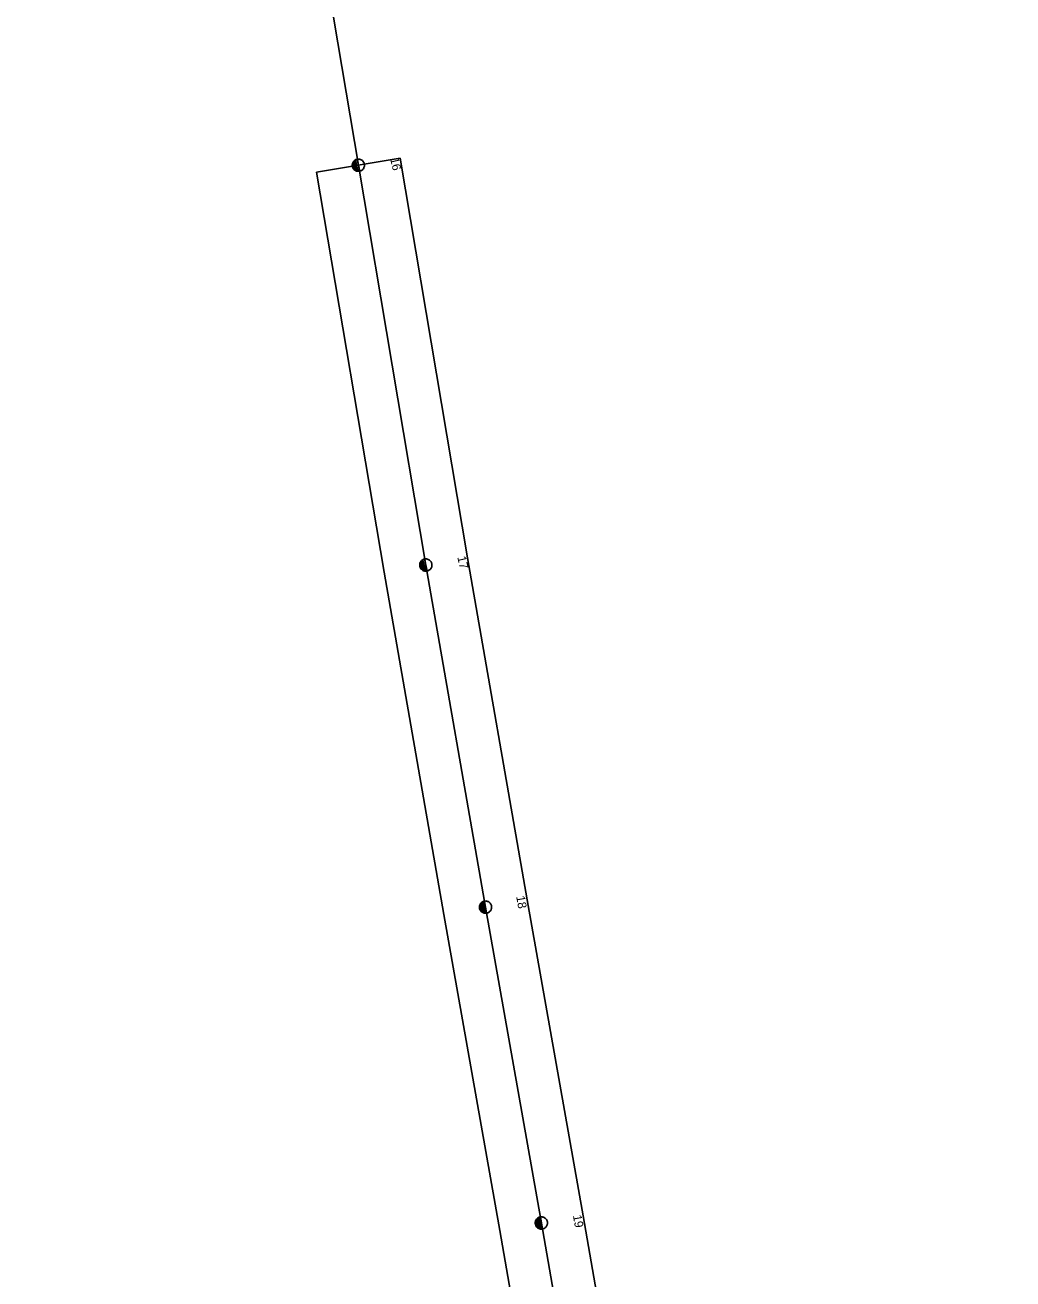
# Model space of a CAD drawing. Extents: x -762349 to -761250, y -1154000 to -1153000.
# Drawn here: x -761620.3 to -761422.1, y -1153503.2 to -1153251.6 of the extents above; entities that cross this region are included whole.
import ezdxf

# ---------------------------------------------------------------- set-up
doc = ezdxf.new("R2010")
doc.units = 0
for name, color, linetype in [('Vrstva 1', 7, 'Continuous'), ('Vrstva 13', 7, 'Continuous'), ('Vrstva 14', 7, 'Continuous'), ('Vrstva 35', 7, 'Continuous')]:
    doc.layers.add(name, color=color, linetype=linetype)

msp = doc.modelspace()

# ---------------------------------------------------------------- linework, layer by layer
at = {"layer": 'Vrstva 1'}
msp.add_lwpolyline([(-761620.31, -1153000), (-761604.55, -1153060.72), (-761583.29, -1153141.72), (-761565.07, -1153210.77), (-761553.44, -1153279.72), (-761539.9, -1153359.95), (-761527.93, -1153428.59), (-761516.72, -1153491.97), (-761505.02, -1153559.26), (-761494.37, -1153619.64), (-761482.3, -1153689.6)], dxfattribs=at)
at = {"layer": 'Vrstva 13'}
for points in [[(-761553.169, -1153280.908), (-761553.045, -1153280.873), (-761552.926, -1153280.825), (-761552.812, -1153280.764), (-761552.705, -1153280.693), (-761552.607, -1153280.61), (-761552.518, -1153280.518), (-761552.439, -1153280.416), (-761552.37, -1153280.308), (-761552.314, -1153280.192), (-761552.27, -1153280.071), (-761552.239, -1153279.946), (-761552.221, -1153279.819), (-761552.217, -1153279.69), (-761552.226, -1153279.562), (-761552.248, -1153279.435), (-761552.283, -1153279.312), (-761552.332, -1153279.193), (-761552.392, -1153279.079), (-761552.464, -1153278.973), (-761552.546, -1153278.874), (-761552.639, -1153278.785), (-761552.74, -1153278.705), (-761552.849, -1153278.637), (-761552.965, -1153278.581), (-761553.086, -1153278.537), (-761553.21, -1153278.506), (-761553.338, -1153278.488), (-761553.466, -1153278.483), (-761553.594, -1153278.492), (-761553.721, -1153278.515), (-761553.845, -1153278.55), (-761553.964, -1153278.598), (-761554.078, -1153278.659), (-761554.184, -1153278.731), (-761554.283, -1153278.814), (-761554.372, -1153278.906), (-761554.451, -1153279.007), (-761554.519, -1153279.116), (-761554.576, -1153279.232), (-761554.62, -1153279.353), (-761554.651, -1153279.478), (-761554.669, -1153279.604), (-761554.673, -1153279.733), (-761554.664, -1153279.862), (-761554.642, -1153279.988), (-761554.606, -1153280.112), (-761554.558, -1153280.231), (-761554.498, -1153280.344), (-761554.426, -1153280.451), (-761554.343, -1153280.549), (-761554.251, -1153280.639), (-761554.149, -1153280.718), (-761554.04, -1153280.786), (-761553.925, -1153280.842), (-761553.804, -1153280.886), (-761553.679, -1153280.918), (-761553.552, -1153280.935), (-761553.423, -1153280.94), (-761553.295, -1153280.931), (-761553.169, -1153280.908)], [(-761554.28, -1153278.876), (-761553.835, -1153280.803)], [(-761554.038, -1153278.643), (-761553.524, -1153280.869)], [(-761553.714, -1153278.51), (-761553.162, -1153280.903)], [(-761554.5, -1153279.203), (-761554.18, -1153280.587)], [(-761539.629, -1153361.138), (-761539.505, -1153361.103), (-761539.386, -1153361.055), (-761539.272, -1153360.994), (-761539.165, -1153360.923), (-761539.067, -1153360.84), (-761538.978, -1153360.747), (-761538.899, -1153360.646), (-761538.83, -1153360.537), (-761538.774, -1153360.422), (-761538.73, -1153360.301), (-761538.699, -1153360.176), (-761538.681, -1153360.049), (-761538.677, -1153359.92), (-761538.686, -1153359.792), (-761538.708, -1153359.665), (-761538.743, -1153359.542), (-761538.792, -1153359.422), (-761538.852, -1153359.309), (-761538.924, -1153359.203), (-761539.006, -1153359.104), (-761539.099, -1153359.015), (-761539.2, -1153358.935), (-761539.309, -1153358.867), (-761539.425, -1153358.811), (-761539.546, -1153358.767), (-761539.67, -1153358.736), (-761539.798, -1153358.718), (-761539.926, -1153358.713), (-761540.054, -1153358.722), (-761540.181, -1153358.745), (-761540.305, -1153358.78), (-761540.424, -1153358.828), (-761540.538, -1153358.889), (-761540.644, -1153358.961), (-761540.743, -1153359.043), (-761540.832, -1153359.136), (-761540.911, -1153359.237), (-761540.979, -1153359.346), (-761541.036, -1153359.462), (-761541.08, -1153359.582), (-761541.111, -1153359.707), (-761541.129, -1153359.834), (-761541.133, -1153359.963), (-761541.124, -1153360.092), (-761541.102, -1153360.218), (-761541.066, -1153360.342), (-761541.018, -1153360.461), (-761540.958, -1153360.574), (-761540.886, -1153360.681), (-761540.803, -1153360.779), (-761540.711, -1153360.869), (-761540.609, -1153360.948), (-761540.5, -1153361.016), (-761540.385, -1153361.072), (-761540.264, -1153361.116), (-761540.139, -1153361.148), (-761540.012, -1153361.165), (-761539.883, -1153361.17), (-761539.755, -1153361.161), (-761539.629, -1153361.138)], [(-761540.96, -1153359.433), (-761540.64, -1153360.817)], [(-761540.74, -1153359.106), (-761540.295, -1153361.033)], [(-761540.498, -1153358.873), (-761539.984, -1153361.099)], [(-761540.174, -1153358.739), (-761539.622, -1153361.133)], [(-761527.722, -1153429.791), (-761527.596, -1153429.763), (-761527.475, -1153429.721), (-761527.358, -1153429.666), (-761527.248, -1153429.6), (-761527.146, -1153429.523), (-761527.052, -1153429.435), (-761526.967, -1153429.338), (-761526.893, -1153429.233), (-761526.831, -1153429.121), (-761526.781, -1153429.002), (-761526.743, -1153428.879), (-761526.719, -1153428.753), (-761526.708, -1153428.625), (-761526.71, -1153428.496), (-761526.726, -1153428.368), (-761526.754, -1153428.244), (-761526.796, -1153428.122), (-761526.851, -1153428.005), (-761526.917, -1153427.895), (-761526.994, -1153427.792), (-761527.082, -1153427.698), (-761527.179, -1153427.614), (-761527.284, -1153427.54), (-761527.397, -1153427.478), (-761527.515, -1153427.428), (-761527.638, -1153427.39), (-761527.764, -1153427.365), (-761527.892, -1153427.354), (-761528.021, -1153427.356), (-761528.148, -1153427.372), (-761528.274, -1153427.401), (-761528.395, -1153427.443), (-761528.512, -1153427.497), (-761528.622, -1153427.564), (-761528.725, -1153427.641), (-761528.819, -1153427.728), (-761528.903, -1153427.825), (-761528.977, -1153427.931), (-761529.039, -1153428.043), (-761529.09, -1153428.162), (-761529.127, -1153428.285), (-761529.151, -1153428.411), (-761529.163, -1153428.539), (-761529.161, -1153428.668), (-761529.145, -1153428.795), (-761529.116, -1153428.921), (-761529.074, -1153429.042), (-761529.02, -1153429.159), (-761528.954, -1153429.269), (-761528.876, -1153429.371), (-761528.788, -1153429.466), (-761528.691, -1153429.55), (-761528.586, -1153429.623), (-761528.473, -1153429.686), (-761528.355, -1153429.736), (-761528.233, -1153429.774), (-761528.106, -1153429.798), (-761527.978, -1153429.809), (-761527.85, -1153429.807), (-761527.722, -1153429.791)], [(-761528.141, -1153427.367), (-761527.715, -1153429.787)], [(-761528.962, -1153428.019), (-761528.715, -1153429.417)], [(-761528.725, -1153427.704), (-761528.382, -1153429.651)], [(-761528.471, -1153427.484), (-761528.075, -1153429.733)], [(-761516.512, -1153493.171), (-761516.386, -1153493.143), (-761516.265, -1153493.101), (-761516.148, -1153493.046), (-761516.038, -1153492.98), (-761515.936, -1153492.903), (-761515.842, -1153492.815), (-761515.757, -1153492.718), (-761515.683, -1153492.613), (-761515.621, -1153492.501), (-761515.571, -1153492.382), (-761515.533, -1153492.259), (-761515.509, -1153492.133), (-761515.498, -1153492.005), (-761515.5, -1153491.876), (-761515.516, -1153491.748), (-761515.544, -1153491.624), (-761515.586, -1153491.502), (-761515.641, -1153491.385), (-761515.707, -1153491.275), (-761515.784, -1153491.172), (-761515.872, -1153491.078), (-761515.969, -1153490.994), (-761516.074, -1153490.92), (-761516.187, -1153490.858), (-761516.305, -1153490.808), (-761516.428, -1153490.77), (-761516.554, -1153490.745), (-761516.682, -1153490.734), (-761516.811, -1153490.736), (-761516.938, -1153490.752), (-761517.064, -1153490.781), (-761517.185, -1153490.823), (-761517.302, -1153490.877), (-761517.412, -1153490.944), (-761517.515, -1153491.021), (-761517.609, -1153491.108), (-761517.693, -1153491.205), (-761517.767, -1153491.311), (-761517.829, -1153491.423), (-761517.88, -1153491.542), (-761517.917, -1153491.665), (-761517.941, -1153491.791), (-761517.953, -1153491.919), (-761517.951, -1153492.048), (-761517.935, -1153492.175), (-761517.906, -1153492.3), (-761517.864, -1153492.422), (-761517.81, -1153492.539), (-761517.744, -1153492.649), (-761517.666, -1153492.751), (-761517.578, -1153492.846), (-761517.481, -1153492.93), (-761517.376, -1153493.003), (-761517.263, -1153493.066), (-761517.145, -1153493.116), (-761517.023, -1153493.154), (-761516.896, -1153493.178), (-761516.768, -1153493.189), (-761516.64, -1153493.187), (-761516.512, -1153493.171)], [(-761517.752, -1153491.399), (-761517.505, -1153492.797)], [(-761517.515, -1153491.084), (-761517.172, -1153493.031)], [(-761517.261, -1153490.864), (-761516.865, -1153493.113)], [(-761516.931, -1153490.747), (-761516.505, -1153493.167)]]:
    msp.add_lwpolyline(points, dxfattribs=at)
at = {"layer": 'Vrstva 35'}
msp.add_lwpolyline([(-761545.06, -1153278.31), (-761561.82, -1153281.13), (-761561.82, -1153281.13), (-761548.28, -1153361.39), (-761536.3, -1153430.06), (-761525.09, -1153493.44), (-761513.39, -1153560.73), (-761502.74, -1153621.1), (-761490.68, -1153691.01), (-761468.7, -1153778.02), (-761438.59, -1153897.09), (-761422.12, -1153892.88), (-761452.22, -1153773.86), (-761471.1, -1153699.44), (-761439.95, -1153702.99), (-761437.75, -1153686.13), (-761475, -1153681.9), (-761486, -1153618.18), (-761496.65, -1153557.79), (-761508.35, -1153490.5), (-761519.56, -1153427.12), (-761531.52, -1153358.51)], close=True, dxfattribs=at)

# ---------------------------------------------------------------- texts
at = {"layer": 'Vrstva 14'}
for s, rotation, p in [('16', 283, (-761547.08, -1153278.4)), ('17', 283, (-761533.61, -1153358.35)), ('18', 280, (-761521.79, -1153426.45)), ('19', 280, (-761510.4, -1153490.48))]:
    msp.add_text(s, height=1.74, rotation=rotation, dxfattribs=at).set_placement(p)

doc.saveas('drawing.dxf')
